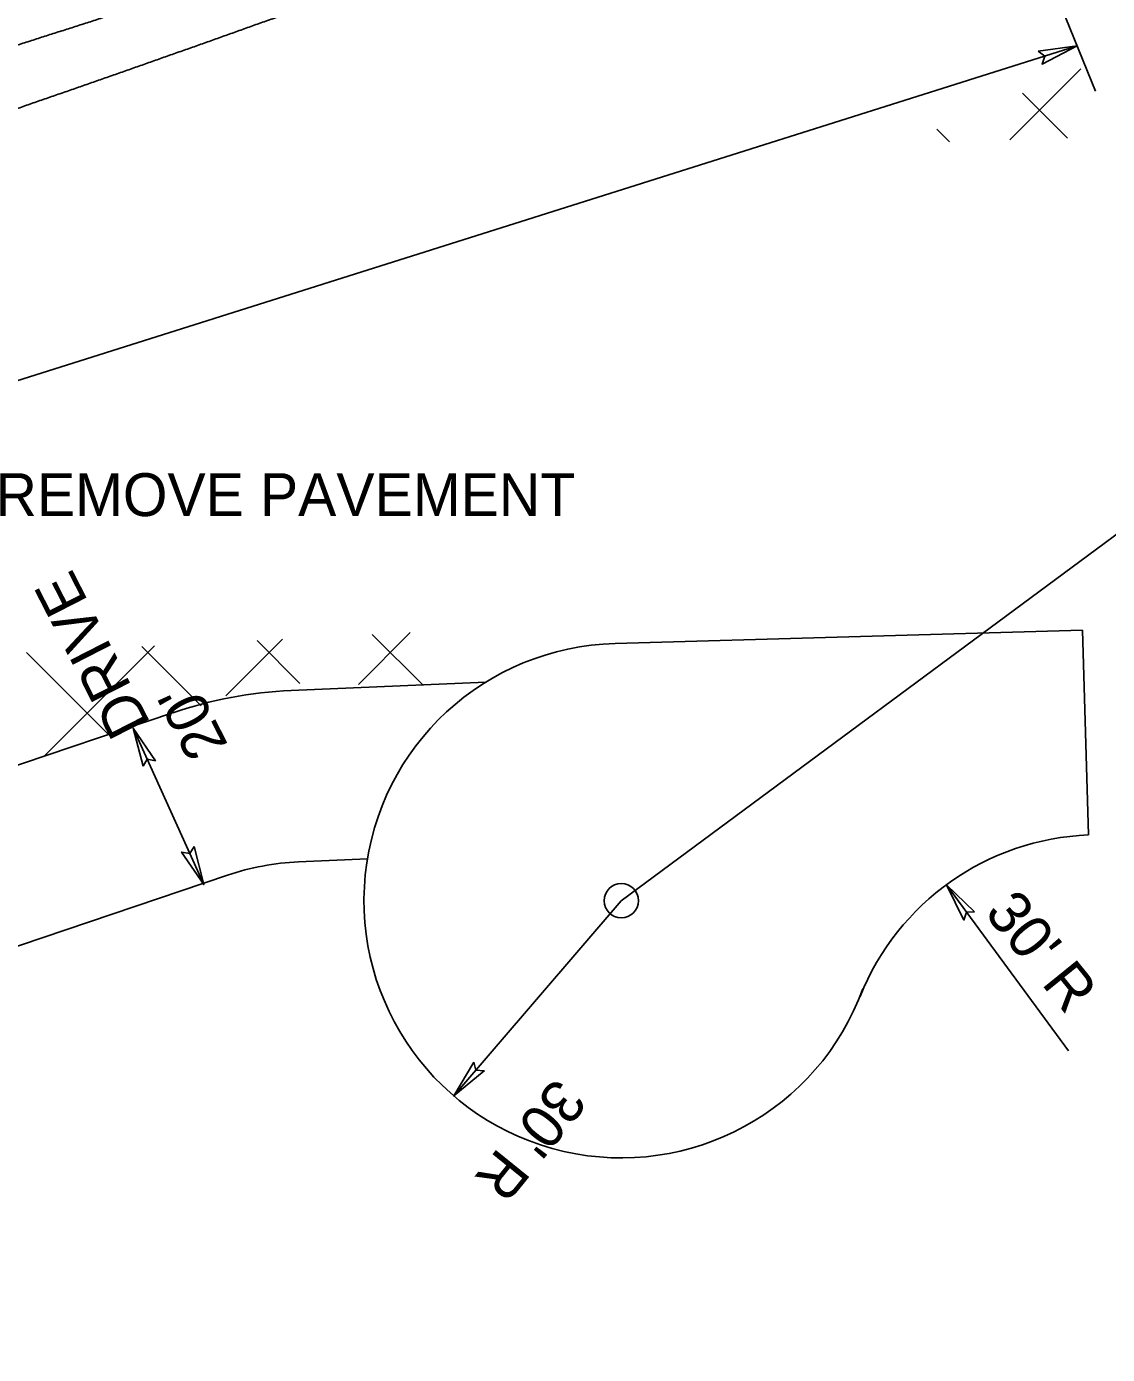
# Model space of a CAD drawing. Extents: x 2389099 to 2405615, y 552200 to 573532.
# Drawn here: x 2391343.4 to 2391469.5, y 552543.8 to 552698.7 of the extents above; entities that cross this region are included whole.
import ezdxf

# ---------------------------------------------------------------- set-up
doc = ezdxf.new("R2010")
doc.units = 0
for name, color, linetype in [('Prop Cable Guiderail Double Face', 7, 'Continuous'), ('Prop Dimension', 7, 'Continuous'), ('Prop Dimension Text', 7, 'Continuous'), ('Prop EOT', 7, 'Continuous'), ('Prop Hatching', 7, 'Continuous'), ('Prop Horizontal Alignment', 7, 'Continuous'), ('Prop Lane Lines', 7, 'Continuous')]:
    doc.layers.add(name, color=color, linetype=linetype)

msp = doc.modelspace()

# ---------------------------------------------------------------- linework, layer by layer
at = {"layer": 'Prop Cable Guiderail Double Face'}
msp.add_arc((2390350.01, 555442.22), 2869, 286.11768, 302.22693, dxfattribs=at)
at = {"layer": 'Prop Dimension'}
for p, q in [((2391459.07, 552713.28), (2391468.06, 552691.16)), ((2391170.44, 552603.05), (2391465.91, 552696.44)), ((2391473.99, 552642.02), (2391412.75, 552596.71)), ((2391355.83, 552616.82), (2391364.07, 552598.6)), ((2391450.67, 552598.57), (2391464.93, 552579.19)), ((2391393.22, 552573.94), (2391412.75, 552596.71))]:
    msp.add_line(p, q, dxfattribs=at)
for points in [[(2391461.39, 552695.82), (2391465.91, 552696.44), (2391461.84, 552694.31), (2391462.15, 552695.25)], [(2391356.98, 552612.41), (2391355.83, 552616.82), (2391358.43, 552613.03), (2391357.46, 552613.23)], [(2391362.93, 552603.02), (2391364.07, 552598.6), (2391361.48, 552602.39), (2391362.45, 552602.2)], [(2391453.96, 552595.4), (2391450.67, 552598.57), (2391452.71, 552594.45), (2391453.01, 552595.39)], [(2391395.56, 552577.86), (2391393.22, 552573.94), (2391396.77, 552576.85), (2391395.79, 552576.93)]]:
    msp.add_lwpolyline(points, close=True, dxfattribs=at)
msp.add_circle((2391412.75, 552596.71), 2, dxfattribs=at)
at = {"layer": 'Prop EOT'}
for p, q in [((2391412.05, 552626.7), (2391466.56, 552628.28)), ((2391467.26, 552604.38), (2391466.56, 552628.28)), ((2391396.96, 552622.22), (2391374.24, 552621.22)), ((2391360.43, 552618.64), (2391182.02, 552558.36)), ((2391383.15, 552601.59), (2391375.12, 552601.24)), ((2391366.83, 552599.69), (2391201.33, 552543.78))]:
    msp.add_line(p, q, dxfattribs=at)
for centre, radius, start, end in [((2390350.01, 555442.22), 2884, 286.11768, 302.22693), ((2390350.01, 555442.22), 2888, 286.11768, 302.22693), ((2391412.75, 552596.71), 30, 91.3413, 339.9956), ((2391376.44, 552571.27), 50, 92.5233, 108.6664), ((2391468.45, 552574.4), 30, 92.2756, 158.1755), ((2391376.44, 552571.27), 30, 92.5233, 108.6666)]:
    msp.add_arc(centre, radius, start, end, dxfattribs=at)
for points in [[(2391334.89, 552694.18), (2391335.67, 552694.43), (2391336.46, 552694.68), (2391337.25, 552694.93), (2391338.04, 552695.17), (2391338.83, 552695.42), (2391339.61, 552695.67), (2391340.41, 552695.93), (2391341.2, 552696.17), (2391341.98, 552696.42), (2391342.77, 552696.67), (2391343.56, 552696.92), (2391344.35, 552697.18), (2391345.13, 552697.43), (2391345.92, 552697.68), (2391346.71, 552697.93), (2391347.49, 552698.18), (2391348.28, 552698.43), (2391349.07, 552698.68), (2391349.86, 552698.94), (2391350.65, 552699.19), (2391351.44, 552699.44), (2391352.22, 552699.7), (2391353.01, 552699.95), (2391353.8, 552700.2), (2391354.58, 552700.46), (2391355.37, 552700.71), (2391356.16, 552700.96), (2391356.94, 552701.22), (2391357.73, 552701.47), (2391358.51, 552701.73), (2391359.31, 552701.98), (2391360.1, 552702.24), (2391360.88, 552702.5), (2391361.67, 552702.75), (2391362.45, 552703.01), (2391363.24, 552703.26), (2391364.02, 552703.52), (2391364.81, 552703.78), (2391365.6, 552704.03), (2391366.38, 552704.29), (2391367.17, 552704.55), (2391367.95, 552704.8), (2391368.74, 552705.06), (2391369.53, 552705.32), (2391370.32, 552705.58), (2391371.1, 552705.84), (2391371.89, 552706.1), (2391372.67, 552706.35), (2391373.46, 552706.61), (2391374.24, 552706.87), (2391375.03, 552707.13), (2391375.81, 552707.39), (2391376.59, 552707.65), (2391377.38, 552707.91), (2391378.16, 552708.17), (2391378.96, 552708.44), (2391379.74, 552708.7), (2391380.53, 552708.96), (2391381.31, 552709.22), (2391382.09, 552709.48), (2391382.88, 552709.74), (2391383.66, 552710), (2391384.45, 552710.27), (2391385.23, 552710.53), (2391386.01, 552710.79), (2391386.8, 552711.05), (2391387.58, 552711.32), (2391388.37, 552711.58), (2391389.16, 552711.85), (2391389.94, 552712.11), (2391390.72, 552712.37), (2391391.51, 552712.64), (2391392.29, 552712.9), (2391393.07, 552713.17)], [(2391337.32, 552687.4), (2391338.1, 552687.67), (2391338.88, 552687.94), (2391339.66, 552688.21), (2391340.45, 552688.48), (2391341.23, 552688.75), (2391342.01, 552689.02), (2391342.8, 552689.29), (2391343.58, 552689.57), (2391344.37, 552689.84), (2391345.15, 552690.11), (2391345.93, 552690.38), (2391346.71, 552690.65), (2391347.49, 552690.92), (2391348.27, 552691.19), (2391349.06, 552691.47), (2391349.84, 552691.74), (2391350.62, 552692.01), (2391351.4, 552692.28), (2391352.19, 552692.56), (2391352.97, 552692.83), (2391353.75, 552693.11), (2391354.53, 552693.38), (2391355.31, 552693.65), (2391356.09, 552693.93), (2391356.87, 552694.2), (2391357.66, 552694.48), (2391358.44, 552694.75), (2391359.22, 552695.03), (2391360, 552695.3), (2391360.78, 552695.58), (2391361.57, 552695.86), (2391362.35, 552696.13), (2391363.13, 552696.41), (2391363.91, 552696.69), (2391364.69, 552696.96), (2391365.47, 552697.24), (2391366.25, 552697.52), (2391367.03, 552697.79), (2391367.81, 552698.07), (2391368.59, 552698.35), (2391369.37, 552698.63), (2391370.14, 552698.91), (2391370.92, 552699.18), (2391371.71, 552699.47), (2391372.49, 552699.74), (2391373.27, 552700.02), (2391374.05, 552700.3), (2391374.83, 552700.58), (2391375.61, 552700.86), (2391376.39, 552701.14), (2391377.17, 552701.42), (2391377.94, 552701.7), (2391378.72, 552701.98), (2391379.5, 552702.26), (2391380.28, 552702.55), (2391381.07, 552702.83), (2391381.85, 552703.11), (2391382.62, 552703.39), (2391383.4, 552703.68), (2391384.18, 552703.96), (2391384.96, 552704.24), (2391385.74, 552704.52), (2391386.51, 552704.81), (2391387.29, 552705.09), (2391388.07, 552705.37), (2391388.85, 552705.66), (2391389.62, 552705.94), (2391390.41, 552706.23), (2391391.19, 552706.51), (2391391.97, 552706.8), (2391392.74, 552707.08), (2391393.52, 552707.36), (2391394.3, 552707.65), (2391395.07, 552707.93)]]:
    msp.add_spline(points, degree=3, dxfattribs=at)
at = {"layer": 'Prop Hatching'}
for p, q in [((2391458.06, 552685.46), (2391466.36, 552693.76)), ((2391464.78, 552685.66), (2391459.54, 552690.9)), ((2391451.05, 552685.25), (2391449.57, 552686.73)), ((2391382.1, 552621.93), (2391388.15, 552627.99)), ((2391345.46, 552613.58), (2391358.31, 552626.43)), ((2391366.62, 552620.6), (2391373.23, 552627.21)), ((2391375.28, 552622.06), (2391370.28, 552627.05)), ((2391389.68, 552621.8), (2391383.72, 552627.76)), ((2391352.95, 552616.11), (2391343.4, 552625.65)), ((2391363.74, 552619.46), (2391356.84, 552626.35))]:
    msp.add_line(p, q, dxfattribs=at)
at = {"layer": 'Prop Horizontal Alignment'}
msp.add_arc((2390350.01, 555442.22), 2865, 286.11768, 302.22693, dxfattribs=at)
at = {"layer": 'Prop Lane Lines'}
for radius in [2900, 2912]:
    msp.add_arc((2390350.01, 555442.22), radius, 286.11768, 302.22693, dxfattribs=at)

# ---------------------------------------------------------------- texts
at = {"layer": 'Prop Dimension Text'}
msp.add_text('REMOVE PAVEMENT', height=5, dxfattribs=at).set_placement((2391339.77, 552641.58))
for s, rotation, p in [('DRIVE', 117.0864, (2391357.91, 552617.36)), ("20'", 117.0864, (2391366.95, 552614.85)), ("30' R", 309.0047, (2391455.01, 552595.25)), ("30' R", 231.036, (2391405.12, 552576.27))]:
    msp.add_text(s, height=5, rotation=rotation, dxfattribs=at).set_placement(p)

doc.saveas('drawing.dxf')
